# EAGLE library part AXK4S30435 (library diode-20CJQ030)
Matsushita P6 NARROW-PITCH CONNECTORS FOR PC BOARDS 30Pin Header NARROW-PITCH (0.6mm) CONNECTORS P6 SERIES FEATURES The product lineup consists of the low profile of: - 3 mm - 4 mm - 5 mm - 6 mm - 7 mm - 8 mm - 9 mm APPLICATIONS Small portable equipment, laptop computers, video equipment, radio communication, cellular telephones, etc. Please send any comments to: messi@users.sourceforge.net
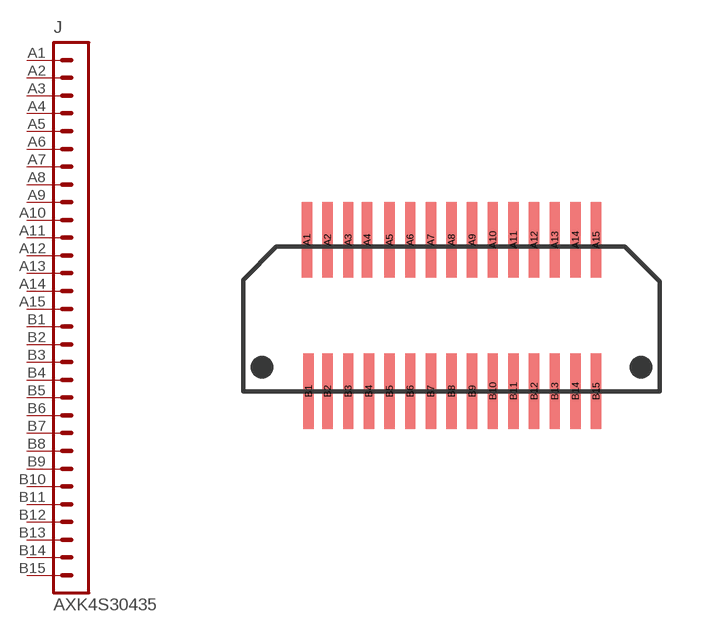
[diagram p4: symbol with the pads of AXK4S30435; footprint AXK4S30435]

Designator prefix J

## AXK4S30435  [AXK4S30435]
A1  1  pas
A2  2  pas
A3  3  pas
A4  4  pas
A5  5  pas
A6  6  pas
A7  7  pas
A8  8  pas
A9  9  pas
A10  10  pas
A11  11  pas
A12  12  pas
A13  13  pas
A14  14  pas
A15  15  pas
B1  16  pas
B2  17  pas
B3  18  pas
B4  19  pas
B5  20  pas
B6  21  pas
B7  22  pas
B8  23  pas
B9  24  pas
B10  25  pas
B11  26  pas
B12  27  pas
B13  28  pas
B14  29  pas
B15  30  pas

## Footprint AXK4S30435 (pad centres in mm)
Matsushita NARROW-PITCH CONNECTORS FOR PC BOARDS 30Pin Header NARROW-PITCH (0.6mm) CONNECTORS P6 SERIES FEATURES The product lineup consists of the low profile of: - 3 mm - 4 mm - 5 mm - 6 mm - 7 mm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
smd 0.3 x 2.2: A1 -4.2,2.3; A2 -3.6,2.3; A3 -3,2.3; A4 -2.45,2.3; A5 -1.8,2.3; A6 -1.2,2.3; A7 -0.6,2.3; A8 0,2.3; A9 0.6,2.3; A10 1.2,2.3; A11 1.8,2.3; A12 2.4,2.3; A13 3,2.3; A14 3.6,2.3; A15 4.2,2.3; B1 -4.15,-2.1; B2 -3.6,-2.1; B3 -3,-2.1; B4 -2.4,-2.1; B5 -1.8,-2.1; B6 -1.2,-2.1; B7 -0.6,-2.1; B8 0,-2.1; B9 0.6,-2.1; B10 1.2,-2.1; B11 1.8,-2.1; B12 2.4,-2.1; B13 3,-2.1; B14 3.6,-2.1; B15 4.2,-2.1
